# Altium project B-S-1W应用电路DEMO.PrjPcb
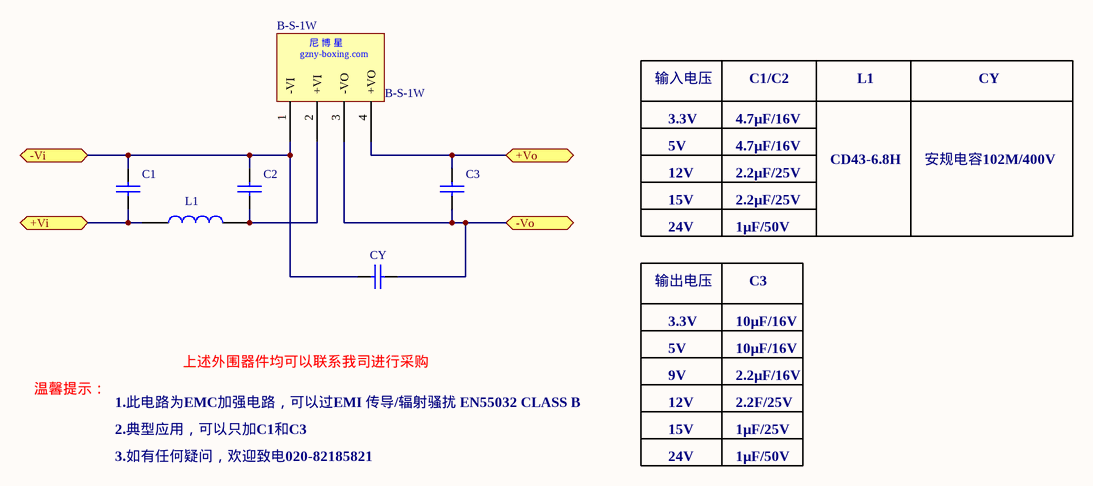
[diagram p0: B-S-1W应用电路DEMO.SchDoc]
1 sheet, 6 parts. Net scope: flat (ports and power ports of the same name join across sheets).
Board file: B-S-1W应用电路DEMO.PcbDoc

## Sheet B-S-1W应用电路DEMO.SchDoc
size 254 x 127 mm; PageSetup: Record=PageOptions|CenterHorizontal=True|CenterVertical=True|PrintScale=1.00|XCorrection=1.00|YCorrection=1.00|PrintKind=1|BorderSize=5000000|LeftOffset=0|BottomOffset=0|Orientation=2|PaperLength=1000|PaperWidth=1000|Scale=100|PaperSource=7|PrintQuality=-4|MediaType=1|DitherType=10|PaperKind=A5|PrintScaleMode=1

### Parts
B-S-1W  B-S-1W  [B-S-1W]
C1  (no value)  [C1206]
C2  (no value)  [C1206]
C3  (no value)  [C1206]
CY  (no value)  [C1206]
L1  (no value)  [CD43]

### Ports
+Vi, +Vo, -Vi, -Vo

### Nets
NetB-S-1W_1: B-S-1W.1(-VI) C1.2 C2.2 CY.1 ; port -Vi
NetB-S-1W_2: B-S-1W.2(+VI) C2.1 L1.2
NetB-S-1W_3: B-S-1W.3(-VO) C3.1 CY.2 ; port -Vo
NetB-S-1W_4: B-S-1W.4(+VO) C3.2 ; port +Vo
NetC1_1: C1.1 L1.1 ; port +Vi

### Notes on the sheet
- 输入电压
- C1/C2
- L1
- CY
- 5V
- 3.3V
- 4.7μF/16V
- 12V
- 15V
- 2.2μF/25V
- CD43-6.8H
- 安规电容102M/400V
- 输出电压
- 24V
- 1μF/50V
- C3
- 10μF/16V
- 温馨提示：
- 1.此电路为EMC加强电路，可以过EMI 传导/辐射骚扰 EN55032 CLASS B
- 上述外围器件均可以联系我司进行采购
- 9V
- 2.2μF/16V
- 2.2F/25V
- 2.典型应用，可以只加C1和C3
- 3.如有任何疑问，欢迎致电020-82185821
- 1μF/25V

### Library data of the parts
C1-C3 CY = CAP
L1 = INDUCTOR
